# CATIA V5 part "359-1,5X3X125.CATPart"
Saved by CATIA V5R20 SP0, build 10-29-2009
Part number: 359-1,5X3X125
Definition: NONE
Nomenclature: 359-1,5X3X125
Source: Unknown
Description: 359-1,5X3X125
Bounding box of the stored display mesh (mm): x -3 to 122, y -3 to 3, z -3 to 3
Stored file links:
  C:\Users\Utente\Desktop\IO LAVORO\3D X SITO CF\X SITO\PLASTICA\359\359-1,5X3X125.CATPart
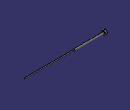
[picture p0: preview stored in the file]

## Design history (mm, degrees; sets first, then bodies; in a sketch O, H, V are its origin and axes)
Body1 "359-1,5X3X125" (main body)
  Solid1: solid without history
